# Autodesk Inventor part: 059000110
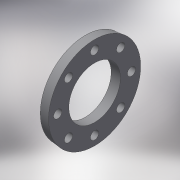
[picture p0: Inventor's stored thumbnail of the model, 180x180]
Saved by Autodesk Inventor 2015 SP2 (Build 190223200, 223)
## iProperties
Created: 2017-10
Part Number: 059000110
Material: Generic
Description: PLASSON BACKING FLANGE PVC 110
Document SubType Name: Modeling
Designer: KIM
Density: 1 g/cm^3
Appearance: Default
Author: KIM
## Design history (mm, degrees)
derived "059000.ipt"
feature "Solid1::059000.ipt"
tag "TaggingFeature1"
body "Solid1"
other parameters: "d0" = 22, "d1" = 135, "d3" = 215.6, "d5" = 18, "d7" = 22, "d8" = 0, "d10" = 360 deg, "E_" = 135, "H_" = 22, "S_" = 18
